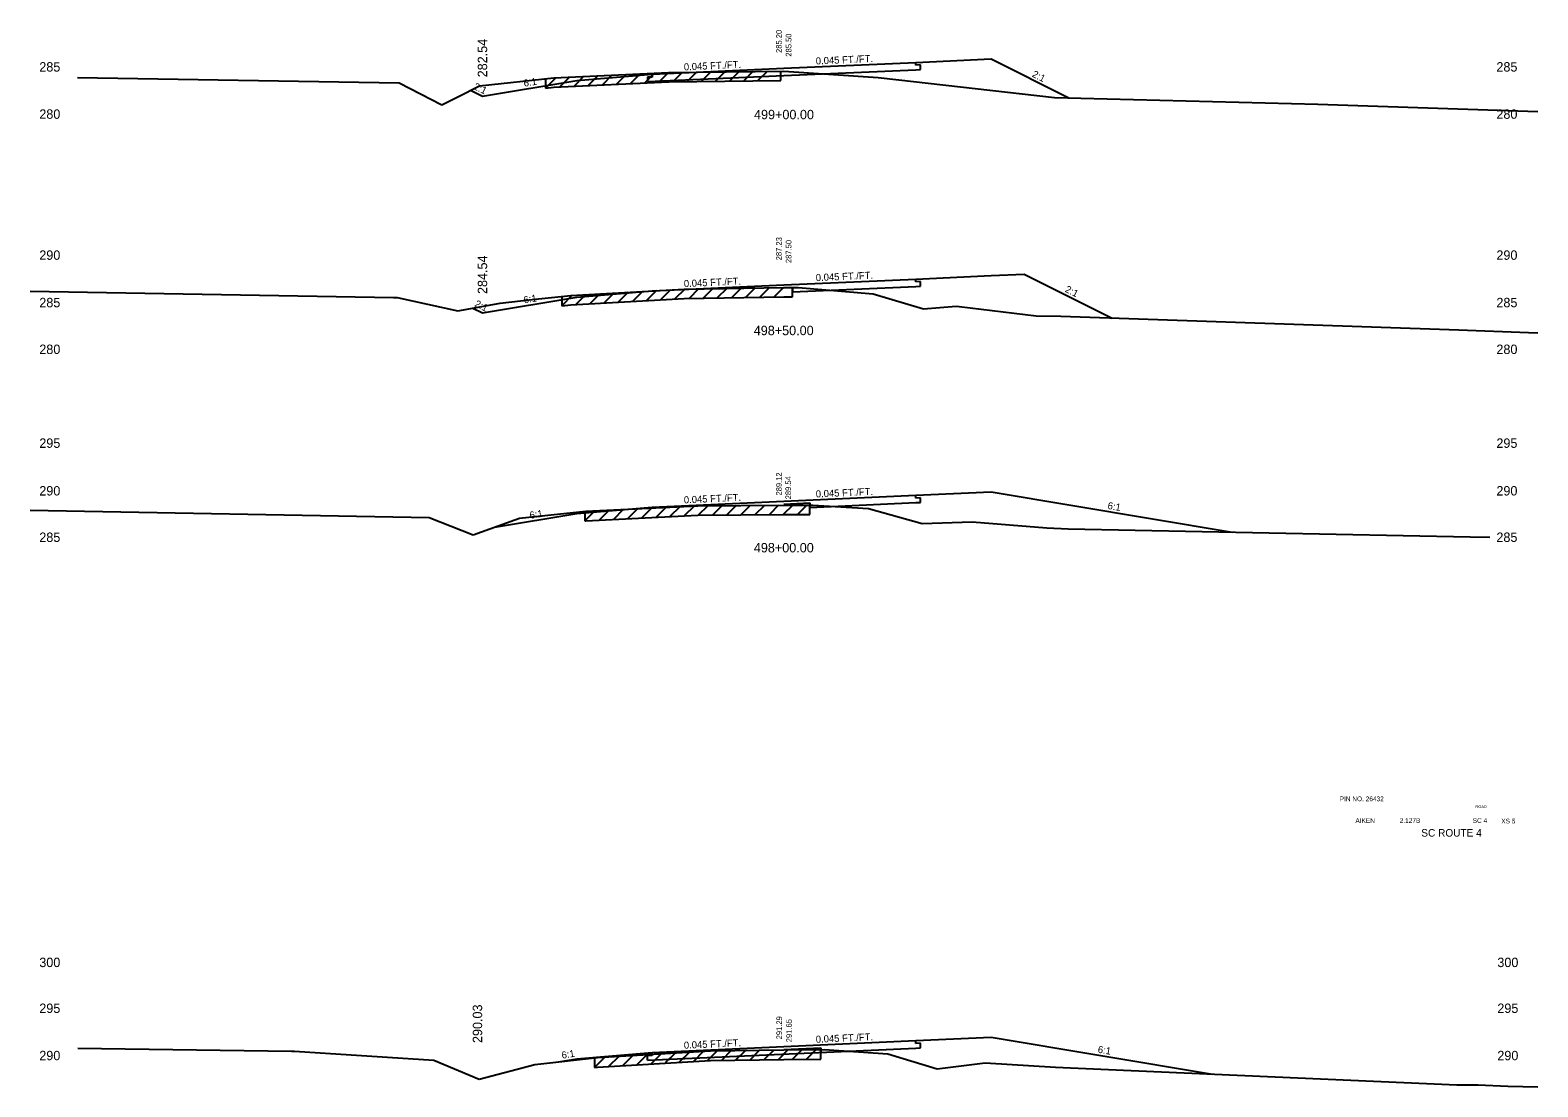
# Model space of a CAD drawing. Extents: x 883 to 1160, y 1002 to 4323.
# Drawn here: x 1000 to 1160, y 1532.4 to 1644.5 of the extents above; entities that cross this region are included whole.
import ezdxf

# ---------------------------------------------------------------- set-up
doc = ezdxf.new("R2010")
doc.units = 0
for name, color, linetype in [('Level 1', 7, 'Continuous'), ('Level 10', 7, 'Continuous'), ('Level 11', 7, 'Continuous'), ('Level 12', 7, 'Continuous'), ('Level 3', 7, 'Continuous'), ('Level 32', 7, 'Continuous'), ('Level 33', 7, 'Continuous'), ('Level 53', 7, 'Continuous'), ('Level 59', 7, 'Continuous'), ('Level 6', 7, 'Continuous'), ('Level 60', 7, 'Continuous'), ('Level 61', 7, 'Continuous'), ('Level 7', 7, 'Continuous')]:
    doc.layers.add(name, color=color, linetype=linetype)

msp = doc.modelspace()

# ---------------------------------------------------------------- linework, layer by layer
at = {"layer": 'Level 11'}
for p, q in [((1094, 1640.83), (1094, 1641.13)), ((1094.5, 1640.85), (1094, 1640.83)), ((1094, 1640.35), (1094.5, 1640.37)), ((1094.5, 1640.37), (1094.5, 1640.85)), ((1094, 1617.83), (1094, 1618.13)), ((1094.5, 1617.85), (1094, 1617.83)), ((1094.5, 1617.37), (1094.5, 1617.85)), ((1094, 1617.35), (1094.5, 1617.37)), ((1066, 1593.81), (1066, 1593.91)), ((1094, 1594.87), (1094, 1595.17)), ((1094.5, 1594.89), (1094, 1594.87)), ((1094, 1594.39), (1094.5, 1594.41)), ((1094.5, 1594.41), (1094.5, 1594.89)), ((1066, 1535.72), (1066, 1536.02)), ((1094, 1536.98), (1094, 1537.28)), ((1094.5, 1537), (1094, 1536.98)), ((1094, 1536.5), (1094.5, 1536.52)), ((1094.5, 1536.52), (1094.5, 1537)), ((1066, 1535.72), (1065.5, 1535.7)), ((1065.5, 1535.22), (1065.5, 1535.7))]:
    msp.add_line(p, q, dxfattribs=at)
at = {"layer": 'Level 12'}
for p, q in [((1080, 1639.72), (1094, 1640.35)), ((1065.5, 1639.09), (1080, 1639.72)), ((1066, 1639.57), (1065.5, 1639.57)), ((1065.5, 1639.57), (1065.5, 1639.09)), ((1066, 1639.87), (1066, 1639.57)), ((1080.9, 1616.76), (1094, 1617.35)), ((1080.9, 1617.24), (1080.9, 1616.76)), ((1082.75, 1593.88), (1094, 1594.39)), ((1082.75, 1594.13), (1082.75, 1593.88)), ((1065.5, 1535.22), (1094, 1536.5)), ((1083.91, 1536.33), (1083.91, 1536.04))]:
    msp.add_line(p, q, dxfattribs=at)
at = {"layer": 'Level 53'}
for p, q in [((1080, 1617.2), (1080.9, 1617.24)), ((1080.9, 1617.24), (1080.9, 1617.24)), ((1080, 1594.24), (1082.75, 1594.36)), ((1082.75, 1594.36), (1082.75, 1594.13)), ((1080, 1536.35), (1083.91, 1536.52)), ((1083.91, 1536.52), (1083.91, 1536.33))]:
    msp.add_line(p, q, dxfattribs=at)
at = {"layer": 'Level 59'}
for p, q in [((1066, 1639.87), (1080, 1640.5)), ((1080, 1640.5), (1094, 1641.13)), ((1080, 1617.5), (1094, 1618.13)), ((1066, 1616.87), (1080, 1617.5)), ((1066, 1593.91), (1080, 1594.54)), ((1080, 1594.54), (1094, 1595.17)), ((1066, 1536.02), (1080, 1536.65)), ((1080, 1536.65), (1094, 1537.28))]:
    msp.add_line(p, q, dxfattribs=at)
at = {"layer": 'Level 6'}
for p, q in [((1094, 1641.13), (1102, 1641.49)), ((1058, 1639.2), (1066, 1639.87)), ((1094, 1618.13), (1102, 1618.49)), ((1102, 1618.49), (1105.5, 1618.65)), ((1058, 1616.2), (1066, 1616.87)), ((1094, 1595.17), (1102, 1595.53)), ((1058, 1593.24), (1066, 1593.91)), ((1094, 1537.28), (1102, 1537.64)), ((1058, 1535.35), (1066, 1536.02))]:
    msp.add_line(p, q, dxfattribs=at)
at = {"layer": 'Level 60'}
for p, q in [((1055.56, 1639.48), (1067.77, 1640.05)), ((1067.77, 1640.05), (1080, 1640.2)), ((1080, 1640.2), (1090, 1639.51)), ((1005.01, 1639.52), (1039.16, 1638.96)), ((1039.16, 1638.96), (1043.7, 1636.61)), ((1045.39, 1637.48), (1047.67, 1638.64)), ((1047.67, 1638.64), (1055.56, 1639.48)), ((1090, 1639.51), (1090.31, 1639.48)), ((1090.31, 1639.48), (1108.7, 1637.41)), ((1043.7, 1636.61), (1045.39, 1637.48)), ((1108.7, 1637.41), (1136.66, 1636.7)), ((1136.66, 1636.7), (1139.85, 1636.58)), ((1139.85, 1636.58), (1160, 1635.93)), ((1000, 1616.83), (1038.57, 1616.18)), ((1038.57, 1616.18), (1038.96, 1616.18)), ((1038.96, 1616.18), (1045.4, 1614.75)), ((1053.28, 1615.95), (1057.38, 1616.39)), ((1057.38, 1616.39), (1069.41, 1617.06)), ((1069.41, 1617.06), (1080, 1617.23)), ((1080, 1617.23), (1081.5, 1617.24)), ((1081.5, 1617.24), (1089.45, 1616.57)), ((1089.45, 1616.57), (1094.82, 1614.96)), ((1045.4, 1614.75), (1049.87, 1615.58)), ((1049.87, 1615.58), (1053.28, 1615.95)), ((1094.82, 1614.96), (1098.27, 1615.26)), ((1098.27, 1615.26), (1098.58, 1615.23)), ((1098.58, 1615.23), (1106.77, 1614.23)), ((1106.77, 1614.23), (1109.38, 1614.18)), ((1109.38, 1614.18), (1151.62, 1612.75)), ((1151.62, 1612.75), (1159.01, 1612.45)), ((1159.01, 1612.45), (1160, 1612.43)), ((1000, 1593.6), (1042.34, 1592.82)), ((1058.98, 1593.47), (1070.87, 1594.05)), ((1070.87, 1594.05), (1080, 1594.12)), ((1080, 1594.12), (1083.07, 1594.13)), ((1083.07, 1594.13), (1088.97, 1593.77)), ((1088.97, 1593.77), (1094.68, 1592.17)), ((1042.34, 1592.82), (1047.01, 1590.97)), ((1047.01, 1590.97), (1051.45, 1592.57)), ((1051.45, 1592.57), (1051.93, 1592.74)), ((1051.93, 1592.74), (1058.98, 1593.47)), ((1094.68, 1592.17), (1099.96, 1592.37)), ((1099.96, 1592.37), (1107.88, 1591.71)), ((1107.88, 1591.71), (1110.14, 1591.61)), ((1110.14, 1591.61), (1152.81, 1590.76)), ((1152.81, 1590.76), (1154.92, 1590.71)), ((1005.06, 1536.47), (1027.74, 1536.15)), ((1027.74, 1536.15), (1028.07, 1536.15)), ((1028.07, 1536.15), (1042.84, 1535.22)), ((1060.22, 1535.48), (1072.2, 1536.19)), ((1072.2, 1536.19), (1080, 1536.29)), ((1080, 1536.29), (1084.25, 1536.34)), ((1084.25, 1536.34), (1091.03, 1535.87)), ((1042.84, 1535.22), (1047.66, 1533.2)), ((1051.01, 1534.08), (1053.57, 1534.76)), ((1053.57, 1534.76), (1060.22, 1535.48)), ((1091.03, 1535.87), (1096.25, 1534.28)), ((1096.25, 1534.28), (1101.35, 1534.94)), ((1101.35, 1534.94), (1108.82, 1534.46)), ((1108.82, 1534.46), (1151.41, 1532.58)), ((1047.66, 1533.2), (1051.01, 1534.08)), ((1151.41, 1532.58), (1153.66, 1532.59)), ((1153.66, 1532.59), (1156.83, 1532.46)), ((1156.83, 1532.46), (1160, 1532.38))]:
    msp.add_line(p, q, dxfattribs=at)
at = {"layer": 'Level 61'}
for p, q in [((1067.74, 1640.04), (1066.69, 1639)), ((1069.21, 1640.06), (1068.19, 1639.05)), ((1070.71, 1640.08), (1069.7, 1639.07)), ((1072.21, 1640.1), (1071.2, 1639.09)), ((1073.71, 1640.12), (1072.7, 1639.11)), ((1075.21, 1640.14), (1074.2, 1639.12)), ((1076.71, 1640.16), (1075.7, 1639.14)), ((1078.21, 1640.17), (1077.2, 1639.16)), ((1079.67, 1639.19), (1079.67, 1640.19)), ((1055.79, 1639.49), (1054.69, 1638.38)), ((1054.69, 1639.38), (1054.69, 1638.38)), ((1054.69, 1638.38), (1055.56, 1638.48)), ((1055.56, 1638.48), (1067.77, 1639.05)), ((1057.24, 1639.56), (1056.19, 1638.51)), ((1058.74, 1639.63), (1057.69, 1638.58)), ((1060.24, 1639.69), (1059.19, 1638.65)), ((1061.74, 1639.76), (1060.69, 1638.72)), ((1063.24, 1639.83), (1062.19, 1638.79)), ((1064.74, 1639.9), (1063.69, 1638.86)), ((1066.24, 1639.97), (1065.19, 1638.93)), ((1067.77, 1639.05), (1079.67, 1639.19)), ((1057.52, 1616.4), (1056.41, 1615.29)), ((1056.41, 1616.29), (1056.41, 1615.29)), ((1057.38, 1615.39), (1069.41, 1616.06)), ((1058.97, 1616.48), (1057.91, 1615.42)), ((1060.47, 1616.56), (1059.41, 1615.51)), ((1061.97, 1616.65), (1060.91, 1615.59)), ((1063.47, 1616.73), (1062.41, 1615.67)), ((1064.97, 1616.81), (1063.91, 1615.76)), ((1066.47, 1616.9), (1065.41, 1615.84)), ((1067.97, 1616.98), (1066.91, 1615.92)), ((1069.47, 1617.06), (1068.42, 1616.01)), ((1069.41, 1616.06), (1080, 1616.23)), ((1070.93, 1617.08), (1069.92, 1616.07)), ((1072.44, 1617.11), (1071.42, 1616.09)), ((1073.94, 1617.13), (1072.92, 1616.12)), ((1075.44, 1617.16), (1074.42, 1616.14)), ((1076.94, 1617.18), (1075.92, 1616.16)), ((1078.44, 1617.2), (1077.42, 1616.19)), ((1079.94, 1617.23), (1078.93, 1616.21)), ((1080, 1616.23), (1080.9, 1616.24)), ((1080.9, 1616.24), (1080.9, 1617.24)), ((1056.41, 1615.29), (1057.38, 1615.39)), ((1062.94, 1593.66), (1061.89, 1592.61)), ((1064.44, 1593.74), (1063.39, 1592.68)), ((1065.95, 1593.81), (1064.89, 1592.76)), ((1067.45, 1593.88), (1066.39, 1592.83)), ((1068.95, 1593.96), (1067.9, 1592.91)), ((1070.45, 1594.03), (1069.4, 1592.98)), ((1071.91, 1594.06), (1070.9, 1593.05)), ((1073.41, 1594.07), (1072.4, 1593.06)), ((1074.92, 1594.08), (1073.91, 1593.08)), ((1076.42, 1594.09), (1075.41, 1593.09)), ((1077.92, 1594.1), (1076.91, 1593.1)), ((1079.42, 1594.12), (1078.41, 1593.11)), ((1080.92, 1594.12), (1079.92, 1593.12)), ((1082.42, 1594.13), (1081.42, 1593.12)), ((1082.75, 1593.13), (1082.75, 1594.13)), ((1059.94, 1593.51), (1058.88, 1592.46)), ((1058.88, 1593.46), (1058.88, 1592.46)), ((1058.88, 1592.46), (1058.98, 1592.47)), ((1058.98, 1592.47), (1070.87, 1593.05)), ((1061.44, 1593.59), (1060.38, 1592.54)), ((1070.87, 1593.05), (1080, 1593.12)), ((1080, 1593.12), (1082.75, 1593.13)), ((1069.96, 1536.06), (1068.89, 1535)), ((1071.46, 1536.15), (1070.39, 1535.08)), ((1072.92, 1536.2), (1071.89, 1535.17)), ((1074.41, 1536.22), (1073.4, 1535.21)), ((1075.91, 1536.24), (1074.9, 1535.23)), ((1077.41, 1536.26), (1076.4, 1535.25)), ((1078.91, 1536.28), (1077.9, 1535.27)), ((1080.41, 1536.3), (1079.4, 1535.28)), ((1081.91, 1536.31), (1080.9, 1535.3)), ((1083.41, 1536.33), (1082.4, 1535.32)), ((1083.91, 1535.33), (1083.91, 1536.33)), ((1060.97, 1535.52), (1059.89, 1534.44)), ((1059.89, 1535.44), (1059.89, 1534.44)), ((1059.89, 1534.44), (1060.22, 1534.48)), ((1060.22, 1534.48), (1072.2, 1535.19)), ((1062.46, 1535.61), (1061.39, 1534.55)), ((1063.96, 1535.7), (1062.89, 1534.64)), ((1065.46, 1535.79), (1064.39, 1534.73)), ((1066.96, 1535.88), (1065.89, 1534.82)), ((1068.46, 1535.97), (1067.39, 1534.91)), ((1072.2, 1535.19), (1080, 1535.29)), ((1080, 1535.29), (1083.91, 1535.33))]:
    msp.add_line(p, q, dxfattribs=at)
at = {"layer": 'Level 7'}
for p, q in [((1102, 1641.49), (1110.24, 1637.37)), ((1048, 1637.54), (1058, 1639.2)), ((1046.74, 1638.17), (1048, 1637.54)), ((1105.5, 1618.65), (1114.81, 1613.99)), ((1048, 1614.54), (1058, 1616.2)), ((1046.98, 1615.04), (1048, 1614.54)), ((1102, 1595.53), (1127.56, 1591.27)), ((1049.27, 1591.79), (1058, 1593.24)), ((1102, 1537.64), (1125.49, 1533.72)), ((1056.06, 1535.03), (1058, 1535.35))]:
    msp.add_line(p, q, dxfattribs=at)

# ---------------------------------------------------------------- texts
at = {"layer": 'Level 1'}
for s, height, p in [('499+00.00', 1, (1076.82, 1635.09)), ('498+50.00', 1, (1076.79, 1612.17)), ('498+00.00', 1, (1076.8, 1589.11)), ('PIN NO. 26432', 0.5, (1138.97, 1562.7)), ('AIKEN', 0.5, (1140.64, 1560.39)), (' 2.127B', 0.5, (1145.15, 1560.39)), ('SC 4', 0.5, (1153.09, 1560.39)), ('XS 5', 0.5, (1156.12, 1560.34)), ('SC ROUTE 4', 0.8, (1147.63, 1558.94))]:
    msp.add_text(s, height=height, dxfattribs=at).set_placement(p)
at = {"layer": 'Level 10'}
for s, p in [('285.20', (1079.76, 1642.13)), ('287.23', (1079.76, 1620.12)), ('289.12', (1079.76, 1595.15)), ('291.29', (1079.79, 1537.42))]:
    msp.add_text(s, height=0.6, rotation=90, dxfattribs=at).set_placement(p)
at = {"layer": 'Level 3'}
for s, height, p in [(' 285', 1, (1000.6, 1640.15)), (' 285', 1, (1155.23, 1640.15)), (' 280', 1, (1000.6, 1635.14)), (' 280', 1, (1155.23, 1635.14)), (' 290', 1, (1000.6, 1620.17)), (' 290', 1, (1155.23, 1620.17)), (' 285', 1, (1000.6, 1615.13)), (' 285', 1, (1155.23, 1615.13)), (' 280', 1, (1000.6, 1610.17)), (' 280', 1, (1155.23, 1610.17)), (' 295', 1, (1000.6, 1600.21)), (' 295', 1, (1155.23, 1600.21)), (' 290', 1, (1000.6, 1595.15)), (' 290', 1, (1155.23, 1595.15)), (' 285', 1, (1000.6, 1590.22)), (' 285', 1, (1155.23, 1590.22)), ('ROAD', 0.3, (1153.38, 1561.97)), (' 300', 1, (1000.6, 1545.09)), (' 300', 1, (1155.33, 1545.09)), (' 295', 1, (1000.6, 1540.22)), (' 295', 1, (1155.33, 1540.22)), (' 290', 1, (1000.6, 1535.2)), (' 290', 1, (1155.33, 1535.2))]:
    msp.add_text(s, height=height, dxfattribs=at).set_placement(p)
at = {"layer": 'Level 32'}
for s, rotation, p in [('0.045 FT./FT.', 2.5766, (1083.39, 1640.9)), ('0.045 FT./FT.', 2.5766, (1069.39, 1640.27)), ('2:1', 333.435, (1106.26, 1639.64)), ('2:1', 333.435, (1046.98, 1638.33)), ('6:1', 9.4623, (1052.43, 1638.53)), ('0.045 FT./FT.', 2.5766, (1069.39, 1617.27)), ('0.045 FT./FT.', 2.5766, (1083.39, 1617.9)), ('6:1', 9.4623, (1052.43, 1615.53)), ('2:1', 333.435, (1109.76, 1616.8)), ('2:1', 333.435, (1047.1, 1615.27)), ('0.045 FT./FT.', 2.5766, (1069.39, 1594.31)), ('0.045 FT./FT.', 2.5766, (1083.39, 1594.94)), ('6:1', 9.4623, (1053.07, 1592.67)), ('6:1', 350.5377, (1114.3, 1593.73)), ('0.045 FT./FT.', 2.5766, (1083.39, 1537.05)), ('6:1', 9.4623, (1056.46, 1535.35)), ('0.045 FT./FT.', 2.5766, (1069.39, 1536.42)), ('6:1', 350.5377, (1113.26, 1536.01))]:
    msp.add_text(s, height=0.75, rotation=rotation, dxfattribs=at).set_placement(p)
at = {"layer": 'Level 33'}
for s, p in [('282.54', (1048.5, 1639.54)), ('284.54', (1048.5, 1616.54)), ('290.03', (1047.97, 1537.03))]:
    msp.add_text(s, height=1, rotation=90, dxfattribs=at).set_placement(p)
at = {"layer": 'Level 59'}
for s, p in [(' 285.50', (1080.79, 1641.51)), (' 287.50', (1080.79, 1619.6)), (' 289.54', (1080.75, 1594.52)), (' 291.65', (1080.83, 1536.89))]:
    msp.add_text(s, height=0.6, rotation=90, dxfattribs=at).set_placement(p)

doc.saveas('drawing.dxf')
